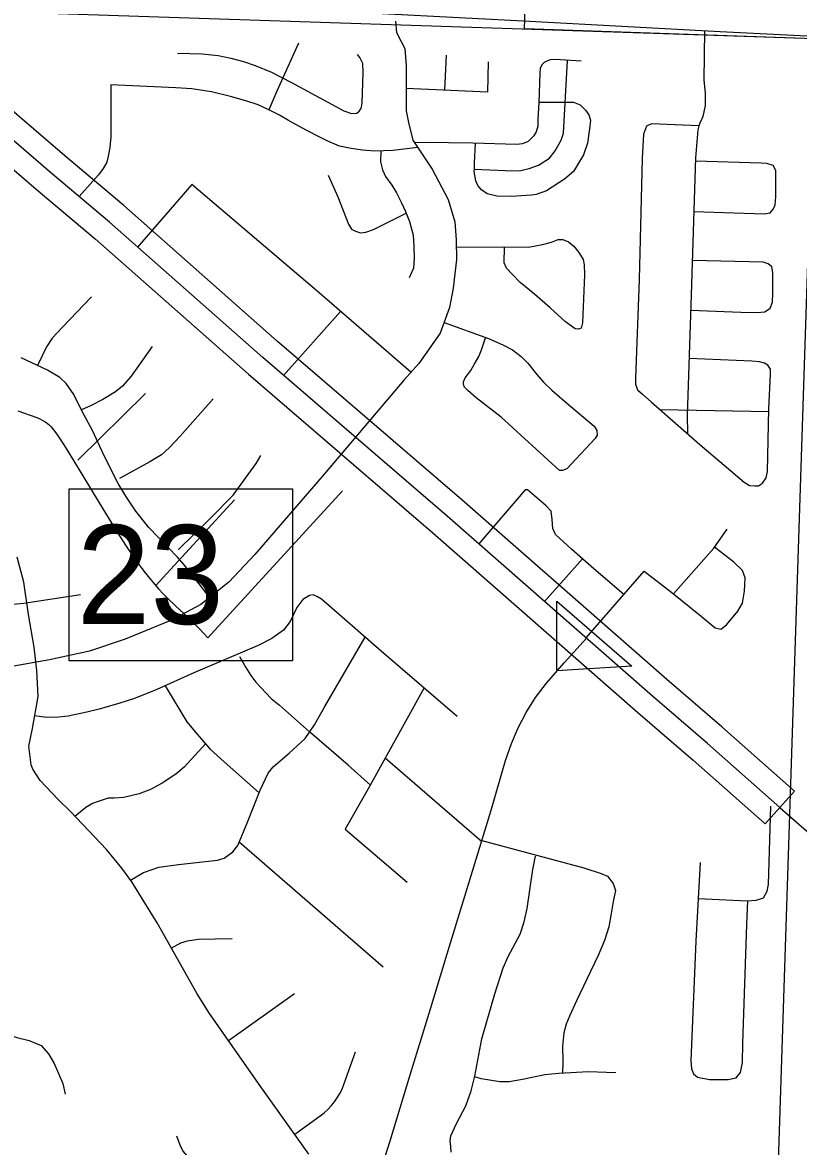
# Model space of a CAD drawing. Extents: x 1219626 to 1426462, y 456797 to 752399.
# Drawn here: x 1363084 to 1366612, y 541593 to 546709 of the extents above; entities that cross this region are included whole.
import ezdxf

# ---------------------------------------------------------------- set-up
doc = ezdxf.new("R2010")
doc.units = 0
for name, color, linetype in [('Bridges', 7, 'Continuous'), ('Local Roads Improved', 7, 'Continuous'), ('Local Roads Paved', 7, 'Continuous'), ('Section Lines', 7, 'Continuous'), ('Section Numbers', 7, 'Continuous'), ('State Route Divided Highway Outline and Fill', 7, 'Continuous'), ('State Routes Highway Center Lines', 7, 'Continuous'), ('Uninventoried Roads and Features', 7, 'Continuous')]:
    doc.layers.add(name, color=color, linetype=linetype)

msp = doc.modelspace()

# ---------------------------------------------------------------- linework, layer by layer
at = {"layer": 'Bridges'}
msp.add_lwpolyline([(1363296.3, 544586), (1364310.8, 544586), (1364310.8, 543803.7), (1363296.3, 543803.7)], close=True, dxfattribs=at)
at = {"layer": 'Local Roads Improved'}
msp.add_line((1364538.4, 544577.2), (1363925.7, 543908.3), dxfattribs=at)
msp.add_lwpolyline([(1363062.1, 544941), (1363148.8, 544910.4), (1363159.2, 544906.1), (1363176.7, 544897.6), (1363189, 544890.2), (1363197.7, 544884), (1363203.9, 544878.9), (1363212.6, 544870.5), (1363220.4, 544861.1), (1363239.4, 544834.8), (1363255.2, 544811.6), (1363281.7, 544770.3), (1363357.4, 544644.7), (1363431.7, 544522.5), (1363506.3, 544400.6), (1363551.3, 544330.2), (1363586.5, 544278.3), (1363614, 544240.2), (1363635.2, 544212.1), (1363668.2, 544170.8), (1363702.8, 544130.6), (1363724.9, 544107), (1363744.9, 544086.9), (1363780.8, 544052.9), (1363835.1, 544002.5), (1363861.7, 543976.7), (1363887.4, 543950), (1363906.6, 543929.1), (1363925.7, 543908.3)], dxfattribs=at)
at = {"layer": 'Local Roads Paved'}
for p, q in [((1365003.6, 546400.4), (1365012.2, 546559.4)), ((1363607.4, 545686), (1363854.4, 545971.5)), ((1364529.9, 545393.8), (1364271.1, 545102)), ((1363637.9, 545184.2), (1363637.9, 545184.2)), ((1365982.8, 544947.8), (1366477.5, 544937.5)), ((1365630.2, 544267.7), (1365457.8, 544073.4)), ((1365171.6, 542981.8), (1364733.3, 543360.6)), ((1364069.3, 542980), (1364724.2, 542410.5)), ((1364021, 542075), (1364320, 542290.1)), ((1364545, 541875.9), (1364597.2, 542023.8)), ((1364321.7, 541649), (1364437.3, 541732.2))]:
    msp.add_line(p, q, dxfattribs=at)
for points in [[(1362310, 546871), (1362666.3, 546856.3), (1363462.2, 546813.8), (1364427.1, 546764.4), (1365361.6, 546716.7), (1366256.3, 546667.3), (1367164.8, 546622.2), (1367542, 546604.9), (1367765.6, 546603.1), (1367974.6, 546610.1), (1368079.5, 546616.2), (1368255.4, 546629.2), (1368565.8, 546674.2), (1368850.2, 546726.3), (1368988.9, 546756.6), (1369250.7, 546826), (1369484.8, 546898.8), (1369633.9, 546949.1), (1369932.1, 547072.2), (1370656.9, 547398.1), (1371339.1, 547704.2), (1372184.4, 548082.1), (1372487, 548217.4), (1372702.8, 548311)], [(1364779.5, 546714.1), (1364784.7, 546663), (1364806.3, 546621.4), (1364822.8, 546590.1), (1364828.9, 546513), (1364828, 546402.9), (1364828, 546305.8), (1364839.3, 546253.8), (1364858.4, 546173.1), (1364945.9, 546041.4), (1365019.6, 545903.5), (1365049.1, 545801.2), (1365055.1, 545718.9), (1365057.7, 545629.6), (1365042.1, 545499.5), (1365024.8, 545411.1), (1364983.2, 545294.1), (1364885.2, 545157.1), (1364819.3, 545082.5), (1364455.2, 544653.4), (1364139.7, 544287.6), (1364021.8, 544161.9), (1363895.2, 544060.4), (1363760.8, 543988.5), (1363551, 543902.6), (1363388, 543847.2), (1363206.8, 543808.1), (1362939, 543760.5)], [(1366185.1, 546671.2), (1366182.2, 546448), (1366188.2, 546384.7), (1366187.4, 546330.1), (1366177.8, 546280.6), (1366164, 546250.3), (1366158.8, 546238.2), (1366155.3, 546220), (1366144, 546092.5), (1366124.9, 545469.2), (1366106.7, 544920.4), (1366107.9, 544837.9)], [(1364338.4, 546613.8), (1364240.4, 546396.2), (1364203.6, 546310.8)], [(1363788.3, 546568.7), (1363901, 546566.1), (1363973, 546558.3), (1364031.5, 546546.1), (1364087.9, 546530.5), (1364141.2, 546512.3), (1364215.3, 546482.4), (1364306.3, 546436), (1364545.6, 546306), (1364580.3, 546294.3), (1364603.7, 546295.2), (1364615, 546304.3), (1364624.1, 546316.8), (1364628, 546342), (1364632.3, 546481.1), (1364631.9, 546521.9), (1364617.6, 546548.7), (1364606.7, 546562.6)], [(1365623.9, 546532.1), (1365507.7, 546539.4), (1365483.8, 546538.1), (1365468.7, 546532.1), (1365455.7, 546526), (1365445.7, 546515.6), (1365438.3, 546498.7), (1365435.7, 546477.9), (1365431.4, 546344.4), (1365426.6, 546266.3), (1365426.6, 546237.3), (1365419.3, 546210.4), (1365408.4, 546192.7), (1365383.3, 546167.1), (1365358.1, 546156.7), (1365330.8, 546152.8), (1365131.4, 546158.8), (1364910.8, 546162.3), (1364866.1, 546161.6)], [(1365141.8, 546158.5), (1365137.9, 546070.4), (1365137.5, 546040.9), (1365279.3, 546035.3), (1365341.7, 546033.6), (1365387.6, 546044.8), (1365430.1, 546059.6), (1365480.8, 546091.7), (1365506.4, 546124.6), (1365532.8, 546173.6), (1365543.7, 546204.8), (1365561.5, 546536)], [(1365201.2, 546529.9), (1365197.8, 546391.2), (1364828.1, 546408.8)], [(1364880.7, 546139.5), (1364767.1, 546125.7), (1364685.6, 546122.2), (1364629.3, 546127), (1364578.1, 546134.8), (1364525.2, 546146.1), (1364471.5, 546167.7), (1364435.1, 546185.9), (1364373.5, 546218.9), (1364292.9, 546263.1), (1364252.1, 546286.5), (1364200.1, 546312.5), (1364155.9, 546333.3), (1364099.6, 546352.4), (1364029.3, 546372.3), (1363942.7, 546393.1), (1363853.4, 546407), (1363780.5, 546410.5), (1363485.8, 546425.2), (1363485.8, 546187.7), (1363480.6, 546139.1), (1363473.6, 546100.1), (1363466.7, 546073.2), (1363451.1, 546043.8), (1363428.6, 546015.1), (1363340.7, 545916.2)], [(1365431.5, 546346.6), (1365558.8, 546345.7), (1365588.7, 546345.7), (1365619.1, 546334.4), (1365644.2, 546310.1), (1365659, 546288.9), (1365666.8, 546264.2), (1365662, 546223.9), (1365653.3, 546159.7), (1365634.3, 546106), (1365589.2, 546030.5), (1365548.4, 545995.9), (1365466.9, 545942.5), (1365419.7, 545926.1), (1365398, 545922.6), (1365307.4, 545916.1), (1365240.2, 545918.3), (1365196, 545929.5), (1365171.3, 545946.9), (1365154, 545966), (1365144.9, 545987.2), (1365138.8, 546020.6), (1365137.2, 546038.7)], [(1366159.1, 546238.9), (1365944.6, 546247.7), (1365921.2, 546237.3), (1365907.3, 546200), (1365901.3, 546089.1), (1365887.4, 545539.4), (1365871.8, 545090.3), (1365871.8, 545062.6), (1365880.5, 545037.5), (1365903, 545016.7), (1365942.9, 544982.8), (1366164, 544788.7), (1366366, 544616.1), (1366390.2, 544601.4), (1366413.6, 544600.5), (1366431, 544600.5), (1366449.2, 544612.7), (1366465.7, 544636.1), (1366470.9, 544664.7), (1366477.8, 544949.9), (1366484.7, 545107.7), (1366484.7, 545130.2), (1366472.6, 545148.4), (1366457.9, 545158.8), (1366435.3, 545164.9), (1366400.6, 545167.5), (1366115.3, 545179.4)], [(1364712.7, 546123.4), (1364711.4, 546074.8), (1364720.1, 546038.3), (1364734.8, 546008), (1364762.6, 545968.1), (1364784.2, 545933.4), (1364807.6, 545887.5), (1364825, 545848.5), (1364844, 545802.5), (1364859.7, 545741), (1364863.1, 545689), (1364864.9, 545636.1), (1364862.3, 545591), (1364841.4, 545546.8)], [(1366136.5, 545848.1), (1366456.1, 545837.6), (1366483, 545842), (1366499.5, 545860.2), (1366506.4, 545879.3), (1366509.9, 545915.7), (1366509.9, 546035.3), (1366496.9, 546057.8), (1366469.1, 546067.4), (1366443.1, 546068.2), (1366143.6, 546077.5)], [(1364850.3, 545117.5), (1364421.9, 545487), (1363854.1, 545971.1)], [(1364473.9, 546014.1), (1364518.1, 545915.2), (1364566.6, 545791.3), (1364579.6, 545768.7), (1364597.8, 545759.2), (1364620.4, 545751.4), (1364644.7, 545754), (1364679.3, 545766.1), (1364828.1, 545841)], [(1365056.1, 545686.9), (1365384.6, 545685.9), (1365447.9, 545698.1), (1365488.6, 545709.3), (1365519.8, 545720.6), (1365541.5, 545720.6), (1365566.6, 545710.2), (1365590.9, 545691.1), (1365613.5, 545662.5), (1365633.4, 545629.6), (1365637.7, 545605.3), (1365638.6, 545560.2), (1365629.9, 545341.8), (1365624.7, 545317.5), (1365611.7, 545312.3), (1365597, 545314), (1365553.6, 545347), (1365482.5, 545409.4), (1365411.5, 545471.8), (1365347.3, 545525.5), (1365308.3, 545564.6), (1365284.9, 545590.6), (1365273.6, 545614), (1365276.2, 545685.5)], [(1366122.6, 545398.9), (1366350.4, 545390.3), (1366423.2, 545388.6), (1366459.6, 545392), (1366483.9, 545408.5), (1366494.3, 545436.3), (1366496, 545477), (1366496, 545570.6), (1366490.8, 545595.8), (1366474.3, 545609.6), (1366451.8, 545617.4), (1366129.7, 545626)], [(1363396.7, 545460.5), (1363265.8, 545322.7), (1363218.1, 545271.5), (1363193, 545232.5), (1363151.3, 545148.2)], [(1365000.6, 545343), (1365203.4, 545270.7), (1365268.4, 545241.2), (1365312.6, 545218.7), (1365350.8, 545189.2), (1365381.1, 545158.8), (1365421.9, 545105.9), (1365453.1, 545071.3), (1365491.2, 545035.7), (1365557.1, 544977.6), (1365683.7, 544871.9), (1365695.8, 544851.9), (1365696.7, 544831.1), (1365687.1, 544814.7), (1365579.6, 544699.4), (1365559.7, 544677.7), (1365539.8, 544669.9), (1365525, 544669.9), (1365259.7, 544911.8), (1365147, 545001.1), (1365108, 545034), (1365094.2, 545049.6), (1365089.8, 545060.9), (1365089.8, 545073), (1365096.8, 545091.2), (1365121.9, 545125), (1365137.5, 545151.9), (1365158.3, 545188.3), (1365170.5, 545219.5), (1365189.5, 545273.3)], [(1363672.6, 545234.5), (1363577.2, 545098.4), (1363538.2, 545053.3), (1363507, 545028.1), (1363448.9, 544992.6), (1363396, 544964.9), (1363351.9, 544945.6)], [(1363931.8, 544094.9), (1363887.2, 544153.4), (1363819.5, 544240.5), (1363789.2, 544274.8), (1363658.7, 544410), (1363598.9, 544484.6), (1363553, 544552.2), (1363518.3, 544611.1), (1363455, 544736.9), (1363401.3, 544851.3), (1363355.3, 544938.8), (1363316.3, 545016), (1363281.6, 545065.4), (1363253.9, 545092.3), (1363196.7, 545127), (1363077.9, 545182.5)], [(1363950.9, 544995.2), (1363800.9, 544826.1), (1363752.4, 544774.1), (1363715.1, 544741.2), (1363662.2, 544709.1), (1363525.2, 544633.7)], [(1363792.2, 544308.6), (1363938.8, 544452.5), (1364041.9, 544557.4), (1364146.8, 544702.2), (1364167.6, 544738.6)], [(1365818.5, 544106), (1365681.9, 544222.5), (1365580.5, 544311), (1365506.8, 544378.6), (1365494.7, 544406.3), (1365493, 544446.2), (1365487.7, 544485.2), (1365465.2, 544509.5), (1365380.2, 544581.5), (1365369.8, 544581.5), (1365158.1, 544336.2)], [(1366044.6, 544108.5), (1366227.2, 544316.2), (1366287.9, 544402)], [(1365646.3, 543908.1), (1365909.9, 544211.3), (1366036.5, 544115), (1366170, 544006.7), (1366233.3, 543953.8), (1366259.3, 543947.7), (1366285.3, 543966.8), (1366337.3, 544030.1), (1366357.3, 544066.5), (1366366.8, 544120.2), (1366369.4, 544180.9), (1366358.2, 544213.9), (1366318.3, 544252.9), (1366230.8, 544321.2)], [(1364386.3, 541558.4), (1364330, 541637.3), (1364175.6, 541854.9), (1363933.8, 542199.1), (1363878.3, 542288.4), (1363695.4, 542610.9), (1363580.1, 542797.3), (1363535, 542859.7), (1363465.6, 542944.7), (1363301.8, 543117.2), (1363245.4, 543172.7), (1363163.9, 543258.5), (1363131, 543310.5), (1363123.2, 543329.6), (1363111.9, 543414.6), (1363128.4, 543496), (1363154.4, 543640.8), (1363148.3, 543759.6), (1363137.1, 543865.4), (1363111, 544013.6), (1363090.2, 544161.9), (1363059.9, 544274.6)], [(1362991.5, 544056.3), (1363089.5, 544066.6), (1363347.6, 544105.3)], [(1365060.6, 543550.4), (1364714.7, 543848.1), (1364443.7, 544084.7), (1364424.8, 544095), (1364405, 544103.6), (1364388.6, 544100.2), (1364358.5, 544083), (1364331, 544046.8), (1364300.9, 543983.2), (1364269.9, 543942.7), (1364217.4, 543905.7), (1364154.6, 543873.9), (1363863, 543749.2), (1363695.2, 543672.6), (1363592.8, 543632.2), (1363526.6, 543610.6), (1363431.9, 543583.1), (1363376, 543570.2), (1363290.9, 543551.3), (1363247, 543547), (1363193.6, 543546.1), (1363138.7, 543553.3)], [(1363574.6, 542804.9), (1363634.1, 542840.6), (1363703.8, 542864.7), (1363792.4, 542875.9), (1363970.5, 542896.6), (1364000.6, 542906), (1364039.4, 542933.6), (1364062.6, 542963.7), (1364106.5, 543069.5), (1364165, 543214.9), (1364200.2, 543291.5), (1364223.5, 543321.6), (1364295.7, 543383.5), (1364368.9, 543450.6), (1364411, 543511.7), (1364459.2, 543596), (1364641.9, 543911.7)], [(1364070.3, 543823.1), (1364098.7, 543772.4), (1364121.9, 543737.1), (1364144.3, 543706.1), (1364167.5, 543682.1), (1364214.9, 543632.2), (1364251.9, 543601.2), (1364389.2, 543480.1)], [(1363732.7, 543689.7), (1363831.1, 543526.3), (1363877.6, 543469.5), (1363936.1, 543403.3), (1364000.6, 543343.1), (1364159.8, 543202)], [(1364909.8, 543680.2), (1364656.2, 543220.9), (1364550.4, 543036.8), (1364832.6, 542796.8)], [(1364665.6, 543237.8), (1364564.2, 543329.3), (1364389.4, 543480.3)], [(1363916.3, 543425.7), (1363819.1, 543319.8), (1363781.2, 543287.2), (1363718.4, 543246.7), (1363665.1, 543217.5), (1363613.5, 543197.7), (1363544.7, 543181.3), (1363500.8, 543178.7), (1363472.4, 543177.9), (1363427.6, 543163.3), (1363401.8, 543153.8), (1363371.7, 543135.7), (1363322.1, 543095.8)], [(1366155.7, 542721.6), (1366379.8, 542711.5), (1366419.7, 542714.1), (1366453.5, 542725.3), (1366470, 542754.8), (1366476.1, 542786), (1366487.3, 543142.3)], [(1365172.9, 542986.3), (1365636.9, 542861.5), (1365715.8, 542836.3), (1365743.5, 542823.3), (1365769.5, 542790.4), (1365779.9, 542758.3), (1365770.4, 542708), (1365760, 542654.3), (1365750.4, 542592.7), (1365730.5, 542530.3), (1365701.9, 542461.8), (1365649.9, 542355.2), (1365603.1, 542255.5), (1365571, 542187), (1365555.4, 542149.7), (1365545.8, 542109.8), (1365539.8, 542050), (1365540.6, 541981.5), (1365539.5, 541926.2)], [(1365032.6, 541568), (1365031.7, 541594), (1365029.1, 541618.3), (1365030.9, 541642.5), (1365057.7, 541697.2), (1365100.2, 541777.8), (1365123.6, 541847.1), (1365141, 541913.9), (1365172.2, 542083.8), (1365231.1, 542288.4), (1365270.1, 542406.3), (1365291.8, 542457.5), (1365346.4, 542558.9), (1365365.5, 542616.1), (1365378.5, 542675.9), (1365403.7, 542854.5), (1365415.8, 542914.3)], [(1366164.8, 542885.7), (1366144.9, 542527.7), (1366123.2, 541984.1), (1366125.8, 541946.8), (1366134.5, 541924.3), (1366153.6, 541908.7), (1366208.2, 541897.4), (1366293.1, 541897.4), (1366329.5, 541905.2), (1366348.6, 541930.4), (1366357.3, 541975.4), (1366359, 542063.9), (1366377.2, 542603.1), (1366381.4, 542711.6)], [(1362817.1, 542777.4), (1362727.4, 542692.4), (1362630.3, 542600.5), (1362573.1, 542539.8), (1362557.5, 542506), (1362548, 542457.5), (1362559.2, 542411.5), (1362574, 542377.7), (1362603.5, 542338.7), (1362702.3, 542269.3), (1362822.8, 542184.4), (1362874.8, 542152.3), (1362930.3, 542129.8), (1363057.7, 542089.9), (1363113.2, 542075.1), (1363167.8, 542052.6), (1363202.5, 542015.3), (1363227.6, 541971.1), (1363267.5, 541879.2), (1363277.9, 541831.5)], [(1363760.4, 542496.3), (1363803.6, 542520.2), (1363834.6, 542529.6), (1363881.9, 542536.5), (1364036.8, 542539.9)], [(1365782.5, 541928.6), (1365655.9, 541933), (1365577, 541928.6), (1365522.4, 541925.2), (1365458.3, 541919.1), (1365356.8, 541897.4), (1365296.2, 541887.9), (1365253.7, 541887.9), (1365168.7, 541900.9), (1365140.1, 541910.4)], [(1363783.4, 541641.7), (1363799, 541600.1), (1363812, 541571.5), (1363831.9, 541548.9), (1363886.5, 541499.5), (1363912.5, 541468.3), (1363925.5, 541444), (1363935.1, 541392.9), (1363938.5, 541335.1)]]:
    msp.add_lwpolyline(points, dxfattribs=at)
msp.add_arc((1364262.1, 541975.7), 300, 305.726, 340.5691, dxfattribs=at)
at = {"layer": 'Section Lines'}
for p, q in [((1361296.2, 546813.7), (1366686.8, 546636.2)), ((1366686.8, 546636.2), (1366508.6, 541177))]:
    msp.add_line(p, q, dxfattribs=at)
at = {"layer": 'State Route Divided Highway Outline and Fill'}
msp.add_line((1366461.6, 543061), (1366594.2, 543210.8), dxfattribs=at)
for points in [[(1358658.1, 549961.1), (1358998.4, 549560.4), (1359317.9, 549254.7), (1359706.6, 548915.2), (1360464.5, 548249.2), (1361358.7, 547480.4), (1362247.2, 546733.7), (1362720.6, 546315.6), (1363146.2, 545949.6), (1363413.8, 545723.6), (1364110.6, 545108.2), (1364949.7, 544386), (1365882.6, 543567.9), (1366132.9, 543352), (1366461.6, 543061)], [(1366594.2, 543210.8), (1366264.5, 543502.6), (1366013.9, 543718.8), (1365080.9, 544536.9), (1364242, 545259), (1363544.6, 545875), (1363275.9, 546101.8), (1362852, 546466.3), (1362377.8, 546885.2), (1361488.2, 547632.8), (1360595.8, 548400.1), (1359838.4, 549065.6), (1359452.9, 549402.4), (1359144.1, 549697.7)]]:
    msp.add_lwpolyline(points, dxfattribs=at)
at = {"layer": 'State Routes Highway Center Lines'}
for p, q in [((1365367, 546679.6), (1365529.7, 552225)), ((1368032.2, 546588.5), (1365367, 546679.6)), ((1365546.8, 543794.2), (1365648.2, 543906.5)), ((1365467.2, 543702), (1365546.8, 543794.2)), ((1365416.3, 543636.5), (1365467.2, 543702)), ((1365374.6, 543568.6), (1365416.3, 543636.5)), ((1365337.2, 543498.2), (1365374.6, 543568.6)), ((1365307.1, 543427.4), (1365337.2, 543498.2)), ((1365280.5, 543349.3), (1365307.1, 543427.4)), ((1365214.5, 543123.2), (1365280.5, 543349.3)), ((1365124.2, 542825.9), (1365214.5, 543123.2)), ((1366528.7, 543135), (1366721.3, 542965.6)), ((1365030.1, 542520.7), (1365124.2, 542825.9)), ((1364938.4, 542219.9), (1365030.1, 542520.7)), ((1364846.8, 541919.6), (1364938.4, 542219.9)), ((1364755.1, 541618.9), (1364846.8, 541919.6)), ((1364721.6, 541514.1), (1364755.1, 541618.9))]:
    msp.add_line(p, q, dxfattribs=at)
msp.add_lwpolyline([(1366527.9, 543135.9), (1366198.7, 543427.3), (1365948.2, 543643.3), (1365015.3, 544461.4), (1364176.3, 545183.6), (1363479.2, 545799.3), (1363211, 546025.7), (1362786.3, 546391), (1362312.5, 546809.4), (1361423.4, 547556.6), (1360530.1, 548324.6), (1359772.5, 548990.4), (1359385.4, 549328.5), (1359071.3, 549629.1)], dxfattribs=at)
msp.add_lwpolyline([(1365513.9, 543757.7), (1365513.9, 544075.4), (1365854.7, 543779)], close=True, dxfattribs=at)
at = {"layer": 'Uninventoried Roads and Features'}
for p, q in [((1363643.2, 545019.9), (1363335.6, 544716.2)), ((1364047.9, 544536.4), (1363688.6, 544145.4))]:
    msp.add_line(p, q, dxfattribs=at)

# ---------------------------------------------------------------- texts
at = {"layer": 'Section Numbers'}
msp.add_text('23', height=450, rotation=359.9997, dxfattribs=at).set_placement((1363330.5, 543971.3))

doc.saveas('drawing.dxf')
